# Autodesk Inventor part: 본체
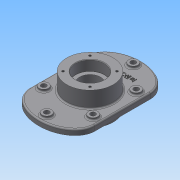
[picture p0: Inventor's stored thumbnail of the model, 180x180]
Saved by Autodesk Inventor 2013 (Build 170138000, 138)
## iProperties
Created: 2015-02
Part Number: 본체
Material: 일반
Document SubType Name: Modeling
Designer: Administrator
Density: 1 g/cm^3
Author: Administrator
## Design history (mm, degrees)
sketch "스케치1" dims "d7" = 70
  geometry: L1 (70, 60)-(70, -60); L2 (-70, -60)-(-70, 60); L3 (-70, 110)-(70, -110); L4 (70, 110)-(-70, -110); 5 further points; 2 other entities
  constraints: 8 end point, 4 midpoint, 1 parallel, 8 other
  dimensions: "d4" = 140 distance between parallel lines of L1 L2; "d6" = 120 distance of point (0, -60) point (0, 60)
extrude "돌출1" new body sketch "스케치1" distance "d8" = 12; taper "d9" = 0 deg
sketch "스케치2"
  geometry: C1 r 50 at (0, 0); 1 further point
  constraints: 1 centre point, 1 coincident
  dimensions: "d10" = 100 diameter of C1
extrude "돌출2" join sketch "스케치2" distance "d11" = 35; taper "d12" = 0 deg
sketch "스케치3"
  geometry: C1 r 50 at (0, 0) reference; C2 r 50 at (0, 0)
  constraints: 1 centre point, 1 coincident
  dimensions: "d14" = 100 diameter of C2
extrude "돌출3" join sketch "스케치3" distance "d15" = 23; taper "d16" = 0 deg
sketch "스케치4"
  geometry: C1 r 50 at (0, 0) reference; C2 r 31 at (0, 0)
  constraints: 1 centre point, 1 coincident
  dimensions: "d17" = 62 diameter of C2
extrude "돌출4" cut sketch "스케치4" distance "d18" = 22; taper "d19" = 0 deg
sketch "스케치5"
  geometry: C1 r 50 at (0, 0) reference; C2 r 31 at (0, 0)
  constraints: 1 centre point, 1 coincident
  dimensions: "d20" = 62 diameter of C2
extrude "돌출5" cut sketch "스케치5" distance "d21" = 22; taper "d22" = 0 deg
sketch "스케치6"
  geometry: C1 r 31 at (0, 0) reference; C2 r 22.5 at (0, 0)
  constraints: 1 centre point, 1 coincident
  dimensions: "d23" = 45 diameter of C2
extrude "돌출6" cut sketch "스케치6" stored distance "d24" = 22; taper "d25" = 0 deg
sketch "스케치7"
  geometry: L1 (28.991, 28.991)-(0, 0); L2 (0, 0)-(122.16, 0); C1 r 31 at (0, 0) reference; C2 r 50 at (0, 0) reference
  constraints: 4 end point, 1 horizontal
  dimensions: "d26" = 41 distance of C1.centre L1.start; "d27" = 45 deg angle of L2 L1
hole "구멍1" sketch "스케치7" at (28.991, 28.991) diameter "d28" = 4.917; stored, may be unused: countersink angle "d32" = 90 deg, drill point angle "d34" = 118 deg; dims "d29" = 10, "d30" = 4, "d31" = 2, "d33" = 13
sketch "스케치8"
  geometry: L1 (0, 0)-(93.266, 0); C1 r 31 at (0, 0) reference; C2 r 50 at (0, 0) reference; 1 further point
  constraints: 2 end point, 1 horizontal
  dimensions: "d38" = 41 distance of C1.centre point (28.991, 28.991); "d39" = 45 deg dimension on C1.centre L1.end point (28.991, 28.991)
hole "구멍2" sketch "스케치8" at (28.991, 28.991) diameter "d40" = 4.917; stored, may be unused: countersink angle "d44" = 90 deg, drill point angle "d46" = 118 deg; dims "d41" = 10, "d42" = 4, "d43" = 2, "d45" = 13
sketch "스케치9"
  geometry: L1 (70, -60)-(70, 60) reference; L2 (-70, 60)-(-70, -60) reference; L3 (70, -60)-(70, 60) reference; L4 (-70, 60)-(-70, -60) reference; L5 (53, 60)-(53, -60); L6 (-53, -60)-(-53, 60); L7 (-80.54, 46.5)-(80.54, 46.5); L8 (-80.54, -46.5)-(80.54, -46.5); C1 r 50 at (0, 0) reference; C2 r 50 at (0, 0) reference; C3 r 10 at (0, 93); C4 r 10 at (-80.54, 46.5); C5 r 10 at (-80.54, -46.5); C6 r 10 at (0, -93); C7 r 10 at (80.54, -46.5); C8 r 10 at (80.54, 46.5); C9 r 10 at (-53, 46.5); C10 r 10 at (53, 46.5); C11 r 10 at (53, -46.5); C12 r 10 at (-53, -46.5); A1 r 93 centre (0, 0) between (0, 93) and (-80.54, 46.5); 4 further points; 4 other entities
  constraints: 11 centre point, 8 end point, 8 point on line, 4 parallel, 3 point on circle, 1 coincident, 1 horizontal alignment, 1 perpendicular, 1 vertical alignment, 23 other
  dimensions: "d50" = 17 distance between parallel lines of L1 L5; "d51" = 20 diameter of C3; "d55" = 360 deg dimension on A1.centre C3.centre (derived); "d57" = 20 diameter of C9; "d58" = 20 diameter of C10; "d59" = 20 diameter of C11; "d60" = 20 diameter of C12
extrude "돌출7" join sketch "스케치9" distance "d61" = 5; taper "d62" = 0 deg
sketch "스케치10"
  geometry: C1 r 10 at (0, 0) reference; C2 r 5.5 at (0, 0); 1 further point
  constraints: 1 centre point, 1 coincident
  dimensions: "d64" = 11 diameter of C2
extrude "돌출8" cut sketch "스케치10" stored distance "d65" = 5; taper "d66" = 0 deg
sketch "스케치11"
  geometry: C1 r 10 at (0, 0) reference; C2 r 5.5 at (0, 0); 1 further point
  constraints: 1 centre point, 1 coincident
  dimensions: "d67" = 11 diameter of C2
extrude "돌출9" cut sketch "스케치11" stored distance "d68" = 5; taper "d69" = 0 deg
sketch "스케치12"
  geometry: C1 r 10 at (0, 0) reference; C2 r 5.5 at (0, 0); 1 further point
  constraints: 1 centre point, 1 coincident
  dimensions: "d70" = 11 diameter of C2
extrude "돌출10" cut sketch "스케치12" stored distance "d71" = 5; taper "d72" = 0 deg
sketch "스케치13"
  geometry: C1 r 10 at (0, 0) reference; C2 r 5.5 at (0, 0); 1 further point
  constraints: 1 centre point, 1 coincident
  dimensions: "d73" = 11 diameter of C2
extrude "돌출11" cut sketch "스케치13" stored distance "d74" = 5; taper "d75" = 0 deg
sketch "스케치14"
  geometry: C1 r 10 at (0, 0) reference; C2 r 5.5 at (0, 0); 1 further point
  constraints: 1 centre point, 1 coincident
  dimensions: "d76" = 11 diameter of C2
extrude "돌출12" cut sketch "스케치14" stored distance "d77" = 11; taper "d78" = 0 deg
sketch "스케치15"
  geometry: C1 r 10 at (0, 0) reference; C2 r 5.5 at (0, 0); 1 further point
  constraints: 1 centre point, 1 coincident
  dimensions: "d79" = 11 diameter of C2
extrude "돌출13" cut sketch "스케치15" stored distance "d81" = 11; taper "d82" = 0 deg
fillet "모깎기1" dims "d83" = 0.3
chamfer "모따기1" distance "d84" = 1; stored, may be unused: second distance "d85" = 2, angle "d86" = 45 deg
fillet "모깎기2" dims "d87" = 3
fillet "모깎기3" dims "d88" = 3
sketch "스케치16"
  geometry: C1 r 53 at (0, 0) reference; 1 further point
  constraints: 1 vertical alignment, 1 other
  dimensions: "d89" = 65 distance of C1.centre point (0, 65)
feature "엠보싱1" sketch "스케치16" dims "d90" = 1, "d91" = 0
node "솔리드1"
pattern_circular "원형 패턴1" dims "d22" = 0, angle "d36" = 360 deg
pattern_circular "원형 패턴2" dims angle "d48" = 360 deg
node "투영된 루프1"
